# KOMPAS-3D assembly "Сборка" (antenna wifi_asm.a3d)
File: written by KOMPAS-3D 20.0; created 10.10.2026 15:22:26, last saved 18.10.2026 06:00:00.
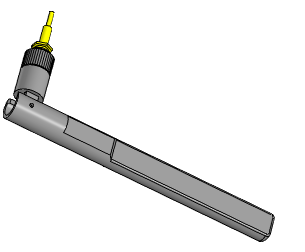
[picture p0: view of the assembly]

Document properties: Полное имя файла: D:\myProjects\Progect_esp32\box_compas\wifi\antenna wifi_asm.a3d

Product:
- Part/product: Сборка
    Масса: 0.120303
  - Component [detail]: Деталь  | Масса: 0.0941381; source file: antenna wifi.m3d
  - Component [detail]: Деталь  | Масса: 0.022341; source file: antenna wifi female.m3d
  - Component [detail]: Деталь  | Масса: 0.00382422; source file: antenna wifi male.m3d

Referenced files in D:\myProjects\Progect_esp32\box_compas\wifi\: antenna wifi female.m3d, antenna wifi.m3d, antenna wifi male.m3d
